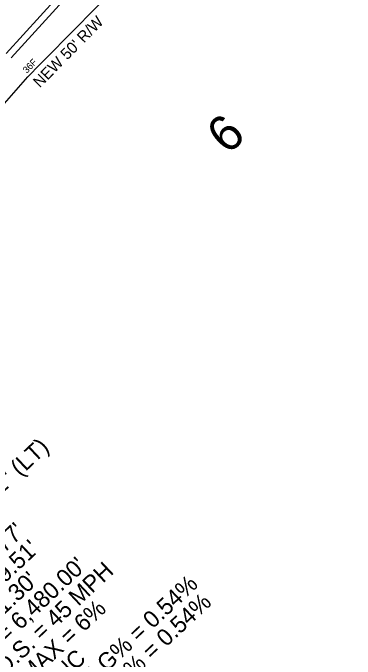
# Model space of a CAD drawing. Extents: x 1623239 to 1625698, y 1118659 to 1120751.
# Drawn here: x 1624676.8 to 1624829.4, y 1119574.5 to 1119862.6 of the extents above; entities that cross this region are included whole.
import ezdxf

# ---------------------------------------------------------------- set-up
doc = ezdxf.new("R2010")
doc.units = 0
for name, color, linetype in [('RD_EX_DV_TX_Prop', 7, 'Continuous'), ('RD_HC_Data', 7, 'Continuous'), ('RD_PD_CstnLmt', 7, 'Continuous'), ('RD_PD_CstnLmt_TX', 7, 'Continuous'), ('RD_PD_DR_ErosCtrl', 7, 'Continuous'), ('RD_PD_RW', 7, 'Continuous'), ('RD_PD_RW_TX', 7, 'Continuous')]:
    doc.layers.add(name, color=color, linetype=linetype)

msp = doc.modelspace()

# ---------------------------------------------------------------- linework, layer by layer
at = {"layer": 'RD_PD_CstnLmt'}
msp.add_line((1624673.75, 1119844.52), (1624707.3, 1119881.4), dxfattribs=at)
at = {"layer": 'RD_PD_DR_ErosCtrl'}
msp.add_line((1624675.98, 1119842.52), (1624709.49, 1119879.36), dxfattribs=at)
at = {"layer": 'RD_PD_RW'}
msp.add_line((1624550.56, 1119682.16), (1624683.49, 1119834.14), dxfattribs=at)
msp.add_arc((1629271.64, 1115329.28), 6430, 133.267464, 135.524786, dxfattribs=at)

# ---------------------------------------------------------------- texts
at = {"layer": 'RD_EX_DV_TX_Prop'}
msp.add_text('6', height=16, rotation=43.1627, dxfattribs=at).set_placement((1624772.67, 1119798.98))
at = {"layer": 'RD_HC_Data'}
for s, p in [('    = 2%%d 17\' 41" (LT)', (1624632.25, 1119610.81)), ("T = 129.77'", (1624645.93, 1119596.22)), ("L = 259.51'", (1624652.77, 1119588.93)), ("R = 6,480.00'", (1624666.45, 1119574.34)), ('D.S. = 45 MPH', (1624673.29, 1119567.05)), ("E = 1.30'", (1624659.61, 1119581.64)), ('P.C. - LG% = 0.54%', (1624693.81, 1119545.17)), ('P.T. - LG% = 0.54%', (1624700.65, 1119537.87)), ('eMAX = 6%', (1624680.13, 1119559.75)), ('e = NC', (1624686.97, 1119552.46))]:
    msp.add_text(s, height=7.5, rotation=43.1627, dxfattribs=at).set_placement(p)
at = {"layer": 'RD_PD_CstnLmt_TX'}
msp.add_text('36F', height=3, rotation=45.3956, dxfattribs=at).set_placement((1624683.01, 1119835.4))
at = {"layer": 'RD_PD_RW_TX'}
msp.add_text("NEW 50' R/W", height=5, rotation=45.5248, dxfattribs=at).set_placement((1624688.84, 1119828.89))

doc.saveas('drawing.dxf')
